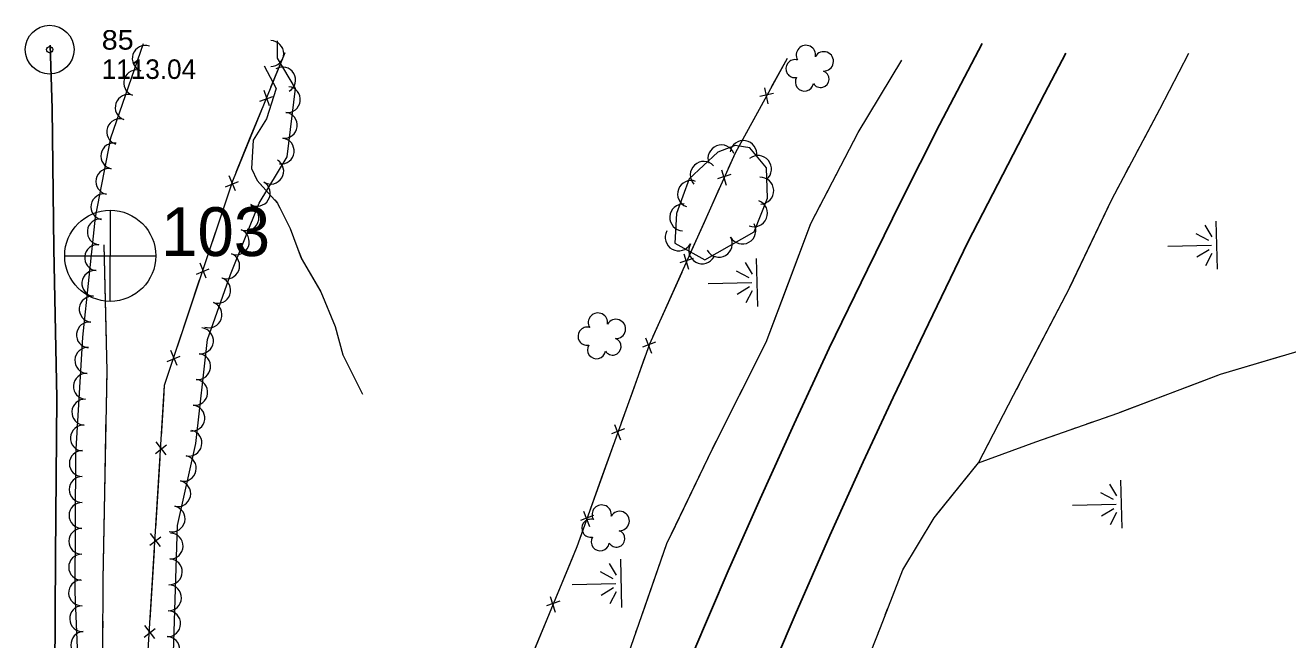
# Model space of a CAD drawing. Extents: x 296527 to 298902, y 45711 to 46924.
# Drawn here: x 297700 to 298087.9, y 46729.1 to 46918 of the extents above; entities that cross this region are included whole.
import ezdxf

# ---------------------------------------------------------------- set-up
doc = ezdxf.new("R2010")
doc.units = 0
doc.header["$LTSCALE"] = 2.4
for name, color, linetype, lineweight in [('11', 7, 'Continuous', 25), ('15', 7, 'Continuous', 13), ('18', 7, 'Continuous', 13), ('19', 7, 'Continuous', 13), ('4', 7, 'Continuous', 13), ('6', 7, 'Continuous', 13)]:
    doc.layers.add(name, color=color, linetype=linetype, lineweight=lineweight)

msp = doc.modelspace()

# ---------------------------------------------------------------- linework, layer by layer
at = {"layer": '11'}
for points in [[(297708.054, 46412.102), (297708.117, 46447.507), (297708.458, 46480.899), (297708.518, 46512.123), (297709.002, 46543.958), (297709.761, 46577.896), (297709.478, 46613.197), (297708.972, 46647.846), (297708.569, 46682.607), (297709.017, 46718.762), (297709.283, 46754.715), (297709.666, 46803.389), (297708.727, 46849.227), (297708.272, 46892.372), (297707.575, 46911.798)], [(297797.637, 46419.407), (297806.038, 46447.108), (297823.092, 46501.139), (297833.508, 46532.828), (297843.333, 46562.228), (297853.578, 46590.979), (297863.061, 46617.192), (297873.203, 46644.121), (297883.41, 46670.443), (297892.882, 46694.741), (297905.062, 46724.82), (297915.884, 46750.233), (297925.772, 46772.377), (297936.243, 46795.47), (297946.994, 46818.695), (297958.748, 46842.839), (297969.032, 46863.808), (297980.865, 46887.359), (297993.929, 46912.343)], [(297820.298, 46412.015), (297829.138, 46440.368), (297837.156, 46466.412), (297845.87, 46494.028), (297854.78, 46520.851), (297860.274, 46536.633), (297868.345, 46560.521), (297877.908, 46588.617), (297888.074, 46615.761), (297897.508, 46640.842), (297906.311, 46664.015), (297914.149, 46683.92), (297925.308, 46710.547), (297936.475, 46736.675), (297947.217, 46761.093), (297957.424, 46783.747), (297966.64, 46803.53), (297977.44, 46826.166), (297989.604, 46851.228), (298001.839, 46875.002), (298013.165, 46896.864), (298019.649, 46909.369)]]:
    msp.add_lwpolyline(points, dxfattribs=at)
at = {"layer": '15'}
for p, q in [((297775.444, 46898.964), (297779.778, 46909.61)), ((297934.044, 46907.735), (297929.181, 46898.872)), ((297927.066, 46898.689), (297928.134, 46893.799)), ((297772.022, 46894.6), (297776.075, 46896.015)), ((297775.003, 46893.2), (297773.38, 46897.935)), ((297929.866, 46896.956), (297925.678, 46896.016)), ((297769.112, 46883.412), (297772.924, 46892.775)), ((297925.966, 46893.014), (297920.436, 46882.937)), ((297764.777, 46872.766), (297769.112, 46883.412)), ((297764.54, 46867.048), (297762.615, 46871.669)), ((297916.782, 46872.034), (297912.683, 46870.76)), ((297913.851, 46873.536), (297915.309, 46868.748)), ((297761.475, 46868.252), (297765.428, 46869.927)), ((297913.212, 46867.791), (297908.512, 46857.301)), ((297759.294, 46856.899), (297762.493, 46866.489)), ((297755.657, 46845.996), (297759.294, 46856.899)), ((297908.512, 46857.301), (297904.378, 46848.075)), ((297755.59, 46840.215), (297753.664, 46844.836)), ((297905.216, 46846.22), (297901.117, 46844.946)), ((297902.286, 46847.723), (297903.744, 46842.934)), ((297752.525, 46841.419), (297756.477, 46843.093)), ((297901.646, 46841.977), (297896.946, 46831.487)), ((297750.343, 46830.066), (297753.542, 46839.656)), ((297746.706, 46819.163), (297750.343, 46830.066)), ((297896.946, 46831.487), (297892.813, 46822.262)), ((297890.574, 46821.821), (297892.395, 46817.159)), ((297746.639, 46813.382), (297744.714, 46818.002)), ((297893.611, 46820.549), (297889.622, 46818.963)), ((297743.574, 46814.586), (297747.527, 46816.26)), ((297890.377, 46816.043), (297886.498, 46805.224)), ((297741.79, 46791.547), (297742.494, 46803.02)), ((297886.498, 46805.224), (297883.085, 46795.708)), ((297881.026, 46795.195), (297882.847, 46790.532)), ((297884.063, 46793.922), (297880.074, 46792.337)), ((297739.943, 46786.318), (297743.33, 46788.954)), ((297743.215, 46785.944), (297740.164, 46789.912)), ((297880.83, 46789.417), (297876.95, 46778.597)), ((297740.76, 46774.786), (297741.38, 46784.877)), ((297876.95, 46778.597), (297873.537, 46769.081)), ((297740.056, 46763.314), (297740.76, 46774.786)), ((297874.515, 46767.296), (297870.526, 46765.711)), ((297871.478, 46768.569), (297873.299, 46763.906)), ((297738.209, 46758.085), (297741.596, 46760.721)), ((297741.481, 46757.711), (297738.43, 46761.679)), ((297739.027, 46746.553), (297739.646, 46756.644)), ((297867.137, 46752.073), (297863.277, 46742.729)), ((297738.322, 46735.08), (297739.027, 46746.553)), ((297864.17, 46740.9), (297860.11, 46739.505)), ((297861.196, 46742.315), (297862.795, 46737.571)), ((297860.726, 46736.553), (297856.338, 46725.929)), ((297736.475, 46729.851), (297739.863, 46732.488)), ((297739.747, 46729.478), (297736.696, 46733.446))]:
    msp.add_line(p, q, dxfattribs=at)
for points in [[(297934.044, 46907.735), (297918.048, 46878.585), (297891.783, 46819.963), (297869.421, 46757.602), (297841.737, 46690.583), (297816.848, 46627.12), (297794.659, 46571.178), (297732.935, 46579.562), (297735.83, 46648.429), (297736.937, 46712.527), (297742.759, 46807.329), (297763.72, 46870.169), (297779.778, 46909.61)], [(297920.436, 46882.937), (297918.048, 46878.585), (297915.944, 46873.889)], [(297742.494, 46803.02), (297742.759, 46807.329), (297744.592, 46812.823)], [(297871.282, 46762.791), (297869.421, 46757.602), (297867.137, 46752.073)]]:
    msp.add_lwpolyline(points, dxfattribs=at)
at = {"layer": '18'}
for points in [[(297736.154, 46912.195), (297726.099, 46883.284), (297721.403, 46859.01), (297717.51, 46822.076), (297715.422, 46785.899), (297715.157, 46743.741), (297716.466, 46714.217)], [(297744.694, 46699.054), (297746.756, 46764.188), (297752.362, 46789.367), (297755.941, 46821.334), (297763.034, 46841.354), (297771.789, 46863.261), (297780.479, 46877.47), (297783.008, 46898.544), (297777.469, 46907.819), (297777.5, 46913.213)]]:
    msp.add_lwpolyline(points, dxfattribs=at)
msp.add_lwpolyline([(297903.909, 46870.716), (297900.032, 46860.121), (297899.518, 46850.923), (297908.747, 46845.883), (297923.949, 46854.42), (297928.046, 46864.787), (297927.658, 46874.098), (297922.588, 46880.23), (297918.076, 46880.972), (297912.758, 46878.931)], close=True, dxfattribs=at)
for centre, radius, start, end in [((297736.814, 46907.75), 3.982, 70.83042, 250.8151), ((297775.393, 46909.244), 3.982, 269.67838, 89.66306), ((297939.805, 46908.813), 2.974, 349.94487, 211.17875), ((297936.445, 46904.619), 2.777, 72.91576, 280.68875), ((297945.321, 46906.853), 2.975, 267.59569, 150.56896), ((297734.199, 46900.229), 3.982, 70.83042, 250.8151), ((297779.038, 46901.127), 3.982, 300.85318, 120.83785), ((297944.314, 46901.423), 2.611, 212.30092, 70.23353), ((297780.497, 46895.11), 3.982, 263.16457, 83.14924), ((297939.361, 46900.482), 2.783, 149.59278, 350.60382), ((297731.583, 46892.708), 3.982, 70.83042, 250.8151), ((297779.548, 46887.204), 3.982, 263.16457, 83.14924), ((297728.967, 46885.187), 3.982, 70.83042, 250.8151), ((297778.599, 46879.298), 3.982, 263.16457, 83.14924), ((297727.153, 46877.76), 3.982, 79.05859, 259.04327), ((297913.838, 46877.028), 4.134, 21.00401, 200.98869), ((297920.584, 46878.367), 4.134, 350.66894, 170.65361), ((297775.377, 46873.121), 3.982, 238.55836, 58.54304), ((297908.41, 46871.942), 4.134, 42.87986, 222.86454), ((297925.121, 46873.77), 4.134, 309.59195, 129.57663), ((297725.641, 46869.943), 3.982, 79.05859, 259.04327), ((297771.222, 46866.328), 3.982, 238.55836, 58.54304), ((297904.52, 46866.09), 4.134, 69.90871, 249.89339), ((297925.783, 46867.11), 4.134, 272.39386, 92.37854), ((297724.128, 46862.125), 3.982, 79.05859, 259.04327), ((297923.883, 46860.14), 4.134, 248.44391, 68.42859), ((297767.76, 46858.796), 3.982, 248.22384, 68.20852), ((297902.13, 46858.882), 4.134, 86.8092, 266.79388), ((297723.016, 46854.429), 3.982, 83.99066, 263.97534), ((297920.297, 46854.851), 4.134, 209.32496, 29.30964), ((297764.805, 46851.402), 3.982, 248.22384, 68.20852), ((297900.709, 46852.738), 4.134, 151.3685, 331.35318), ((297913.089, 46850.803), 4.134, 209.32496, 29.30964), ((297722.181, 46846.51), 3.982, 83.99066, 263.97534), ((297907.965, 46848.776), 4.134, 151.3685, 331.35318), ((297761.85, 46844.007), 3.982, 248.22384, 68.20852), ((297721.346, 46838.591), 3.982, 83.99066, 263.97534), ((297759.087, 46836.453), 3.982, 250.49864, 70.48332), ((297720.512, 46830.672), 3.982, 83.99066, 263.97534), ((297756.427, 46828.947), 3.982, 250.49864, 70.48332), ((297875.925, 46826.548), 2.974, 349.94487, 211.17875), ((297719.677, 46822.753), 3.982, 83.99066, 263.97534), ((297872.565, 46822.354), 2.777, 72.91576, 280.68875), ((297881.441, 46824.588), 2.975, 267.59569, 150.56896), ((297753.8, 46820.946), 3.982, 263.61948, 83.60415), ((297880.434, 46819.158), 2.611, 212.30092, 70.23353), ((297719.184, 46814.906), 3.982, 86.70443, 266.68911), ((297875.481, 46818.217), 2.783, 149.59278, 350.60382), ((297752.915, 46813.032), 3.982, 263.61948, 83.60415), ((297718.725, 46806.956), 3.982, 86.70443, 266.68911), ((297752.029, 46805.119), 3.982, 263.61948, 83.60415), ((297718.266, 46799.007), 3.982, 86.70443, 266.68911), ((297751.143, 46797.206), 3.982, 263.61948, 83.60415), ((297717.807, 46791.057), 3.982, 86.70443, 266.68911), ((297750.261, 46789.519), 3.982, 257.45572, 77.4404), ((297717.489, 46783.211), 3.982, 89.64751, 269.63219), ((297748.53, 46781.747), 3.982, 257.45572, 77.4404), ((297717.439, 46775.248), 3.982, 89.64751, 269.63219), ((297746.8, 46773.974), 3.982, 257.45572, 77.4404), ((297717.389, 46767.285), 3.982, 89.64751, 269.63219), ((297745.069, 46766.202), 3.982, 257.45572, 77.4404), ((297877.076, 46767.525), 2.974, 349.94487, 211.17875), ((297882.592, 46765.565), 2.975, 267.59569, 150.56896), ((297717.339, 46759.323), 3.982, 89.64751, 269.63219), ((297873.716, 46763.331), 2.777, 72.91576, 280.68875), ((297744.472, 46757.894), 3.982, 268.19441, 88.17909), ((297876.632, 46759.194), 2.783, 149.59278, 350.60382), ((297881.585, 46760.135), 2.611, 212.30092, 70.23353), ((297717.289, 46751.36), 3.982, 89.64751, 269.63219), ((297744.22, 46749.935), 3.982, 268.19441, 88.17909), ((297717.254, 46743.504), 3.982, 92.54631, 272.53099), ((297743.968, 46741.976), 3.982, 268.19441, 88.17909), ((297717.606, 46735.549), 3.982, 92.54631, 272.53099), ((297743.716, 46734.018), 3.982, 268.19441, 88.17909), ((297717.959, 46727.594), 3.982, 92.54631, 272.53099), ((297743.464, 46726.059), 3.982, 268.19441, 88.17909)]:
    msp.add_arc(centre, radius, start, end, dxfattribs=at)
at = {"layer": '19'}
for p, q in [((298041.081, 46878.091), (298042.031, 46879.871)), ((297951.777, 46877.067), (297952.697, 46878.835)), ((297949.019, 46871.761), (297949.938, 46873.53)), ((298038.231, 46872.748), (298039.181, 46874.529)), ((297946.261, 46866.456), (297947.18, 46868.224)), ((298035.38, 46867.406), (298036.33, 46869.186)), ((298020.904, 46837.413), (298033.516, 46863.826)), ((298062.358, 46856.505), (298064.541, 46852.875)), ((298066.279, 46842.961), (298065.903, 46857.751)), ((298063.635, 46851.751), (298059.73, 46853.853)), ((297724.904, 46820.763), (297724.234, 46850.444)), ((297783.736, 46849.146), (297784.732, 46846.53)), ((298051.025, 46850.001), (298064.441, 46850.341)), ((298063.706, 46848.947), (298059.913, 46846.65)), ((297921.129, 46845.055), (297923.312, 46841.425)), ((297925.05, 46831.511), (297924.674, 46846.301)), ((298062.673, 46844.134), (298064.668, 46847.871)), ((297922.406, 46840.301), (297918.501, 46842.403)), ((297909.796, 46838.551), (297923.212, 46838.891)), ((297922.477, 46837.497), (297918.684, 46835.2)), ((297921.444, 46832.684), (297923.439, 46836.421)), ((297725.042, 46814.622), (297724.996, 46816.669)), ((297725.05, 46808.48), (297725.088, 46810.528)), ((297919.444, 46804.331), (297920.339, 46806.112)), ((298004.592, 46806.08), (298005.524, 46807.87)), ((298036.401, 46799.016), (298061.027, 46808.354)), ((297724.936, 46802.339), (297724.974, 46804.386)), ((298001.798, 46800.708), (298002.729, 46802.499)), ((297724.307, 46768.561), (297724.859, 46798.245)), ((297916.759, 46798.989), (297917.654, 46800.77)), ((297914.074, 46793.646), (297914.969, 46795.427)), ((297999.005, 46795.335), (297999.936, 46797.126)), ((298020.977, 46793.603), (298022.691, 46794.202)), ((298026.12, 46795.4), (298027.835, 46795.999)), ((298031.264, 46797.198), (298032.979, 46797.797)), ((298033.062, 46776.886), (298035.245, 46773.256)), ((298036.983, 46763.342), (298036.607, 46778.132)), ((298021.729, 46770.382), (298035.145, 46770.722)), ((298034.339, 46772.132), (298030.434, 46774.234)), ((298034.41, 46769.328), (298030.617, 46767.031)), ((298033.377, 46764.515), (298035.372, 46768.252)), ((297879.357, 46752.545), (297881.54, 46748.915)), ((297883.278, 46739.001), (297882.902, 46753.791)), ((297880.634, 46747.791), (297876.729, 46749.893)), ((297868.024, 46746.041), (297881.44, 46746.381)), ((297880.705, 46744.987), (297876.912, 46742.69)), ((297879.672, 46740.174), (297881.667, 46743.911)), ((297964.197, 46736.704), (297964.93, 46738.585)), ((297723.851, 46732.734), (297723.86, 46734.781)), ((297887.595, 46731.382), (297888.251, 46733.264))]:
    msp.add_line(p, q, dxfattribs=at)
for points in [[(297992.799, 46783.396), (298010.43, 46789.917), (298035.614, 46798.718), (298067.174, 46810.685), (298113.924, 46824.524), (298146.474, 46833.059), (298174.587, 46839.915), (298200.18, 46846.537), (298222.733, 46856.305), (298245.774, 46868.244), (298263.763, 46874.627), (298274.192, 46877.472), (298285.769, 46883.285), (298300.885, 46891.268), (298313.666, 46900.337), (298325.19, 46909.523), (298328.679, 46913.623)], [(297727.661, 46234.355), (297732.98, 46260.083), (297738.903, 46291.249), (297745.297, 46315.358), (297756.148, 46347.424), (297765.976, 46376.737), (297771.06, 46400.488), (297779.797, 46430.522), (297789.42, 46456.6), (297797.023, 46481.408), (297804.603, 46509.862), (297813.358, 46538.762), (297823.513, 46568.595), (297833.773, 46597.545), (297845.531, 46622.563), (297856.504, 46652.912), (297867.391, 46677.903), (297881.799, 46714.74), (297897.082, 46758.62), (297911.1, 46787.728), (297927.574, 46820.51), (297941.355, 46857.021), (297955.912, 46885.019), (297969.251, 46907.237)], [(297849.168, 46407.743), (297855.933, 46436.406), (297862.339, 46459.994), (297871.416, 46490.098), (297879.057, 46517.15), (297883.894, 46539.3), (297893.627, 46561.368), (297905.47, 46587.876), (297917.581, 46616.135), (297926.493, 46644.311), (297933.689, 46666.354), (297943.064, 46684.718), (297951.029, 46703.202), (297962.693, 46732.843), (297969.576, 46750.509), (297979.206, 46766.525), (297992.799, 46783.396), (298003.624, 46804.221), (298020.877, 46837.356), (298033.907, 46864.644), (298048.564, 46892.117), (298057.459, 46909.387)], [(297954.536, 46882.372), (297955.912, 46885.019), (297969.251, 46907.237)], [(298043.931, 46883.433), (298048.564, 46892.117), (298057.459, 46909.387)], [(297773.352, 46905.489), (297777, 46898.528), (297774.035, 46889.232), (297769.989, 46882.638), (297769.501, 46873.96), (297771.227, 46870.261), (297777.453, 46863.302), (297781.329, 46855.464), (297784.781, 46846.403), (297790.781, 46835.988), (297795.219, 46825.387), (297797.528, 46816.644), (297803.599, 46804.595)], [(297773.352, 46905.489), (297777, 46898.528), (297774.035, 46889.232), (297769.989, 46882.638), (297769.501, 46873.96), (297771.227, 46870.261), (297772.862, 46868.433)], [(297776.595, 46864.262), (297777.453, 46863.302), (297778.123, 46861.947)], [(297933.497, 46836.202), (297941.355, 46857.021), (297944.422, 46862.919)], [(297780.604, 46856.93), (297781.329, 46855.464), (297781.743, 46854.377)], [(297719.624, 46441.276), (297720.777, 46482.963), (297722.616, 46521.753), (297722.968, 46553.002), (297721.513, 46576.337), (297723.475, 46608.269), (297723.635, 46642.928), (297723.906, 46668.367), (297723.733, 46705.736), (297723.916, 46747.538), (297725.109, 46811.661), (297724.234, 46850.444)], [(297787.507, 46841.671), (297790.781, 46835.988), (297795.219, 46825.387), (297797.528, 46816.644), (297803.599, 46804.595)], [(298007.389, 46811.451), (298020.877, 46837.356), (298020.904, 46837.413)], [(297922.128, 46809.674), (297927.574, 46820.51), (297933.497, 46836.202)], [(298061.027, 46808.354), (298067.174, 46810.685), (298086.125, 46816.295)], [(297899.703, 46764.063), (297911.1, 46787.728), (297912.284, 46790.085)], [(297980.348, 46767.942), (297992.799, 46783.396), (297997.143, 46791.753)], [(297992.799, 46783.396), (298010.43, 46789.917), (298017.547, 46792.404)], [(297723.878, 46738.876), (297723.916, 46747.538), (297724.307, 46768.561)], [(297966.396, 46742.347), (297969.576, 46750.509), (297979.206, 46766.525), (297980.348, 46767.942)], [(297889.562, 46737.029), (297897.082, 46758.62), (297899.703, 46764.063)], [(297961.993, 46731.064), (297962.693, 46732.843), (297962.732, 46732.943)]]:
    msp.add_lwpolyline(points, dxfattribs=at)
at = {"layer": '4'}
for p, q in [((297726.017, 46861.101), (297725.952, 46833.247)), ((297712.108, 46847.071), (297740.013, 46847.058))]:
    msp.add_line(p, q, dxfattribs=at)
msp.add_circle((297726.069, 46847.079), 14, dxfattribs=at)
at = {"layer": '6'}
for radius in [7.5, 0.96]:
    msp.add_circle((297707.454, 46910.456), radius, dxfattribs=at)

# ---------------------------------------------------------------- texts
at = {"layer": '4'}
msp.add_text('103', height=15, dxfattribs=at).set_placement((297741.721, 46847.009))
at = {"layer": '6', "width": 1.1}
msp.add_text('85', height=6, dxfattribs=at).set_placement((297723.454, 46910.456))
at = {"layer": '6'}
msp.add_text('1113.04', height=6, dxfattribs=at).set_placement((297723.454, 46901.456))

doc.saveas('drawing.dxf')
